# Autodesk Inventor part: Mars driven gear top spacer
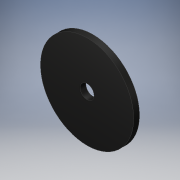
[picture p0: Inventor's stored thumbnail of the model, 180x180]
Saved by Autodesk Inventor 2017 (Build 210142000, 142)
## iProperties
Created: 2016-07
Part Number: Mars driven gear top spacer
Material: Generic
Document SubType Name: Modeling
Designer: Stan
Density: 1 g/cm^3
Appearance: Glossy - Black
Author: Stan
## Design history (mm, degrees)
sketch "Sketch1"
  geometry: C1 r 25.4 at (0, 0); C2 r 3.81 at (0, 0); 1 further point
  constraints: 2 centre point, 2 coincident
  dimensions: "d0" = 50.8 diameter of C1; "d1" = 7.62 diameter of C2
extrude "Extrusion1" new body sketch "Sketch1" distance "d2" = 3.175; taper "d3" = 0 deg
body "Solid1"
